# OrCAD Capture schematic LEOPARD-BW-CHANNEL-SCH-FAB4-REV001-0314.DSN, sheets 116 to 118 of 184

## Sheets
116 055_DDR4 DIMM CPU0 CHB-2: size A3; title: DDR4 DIMM CPU0 CHB-2
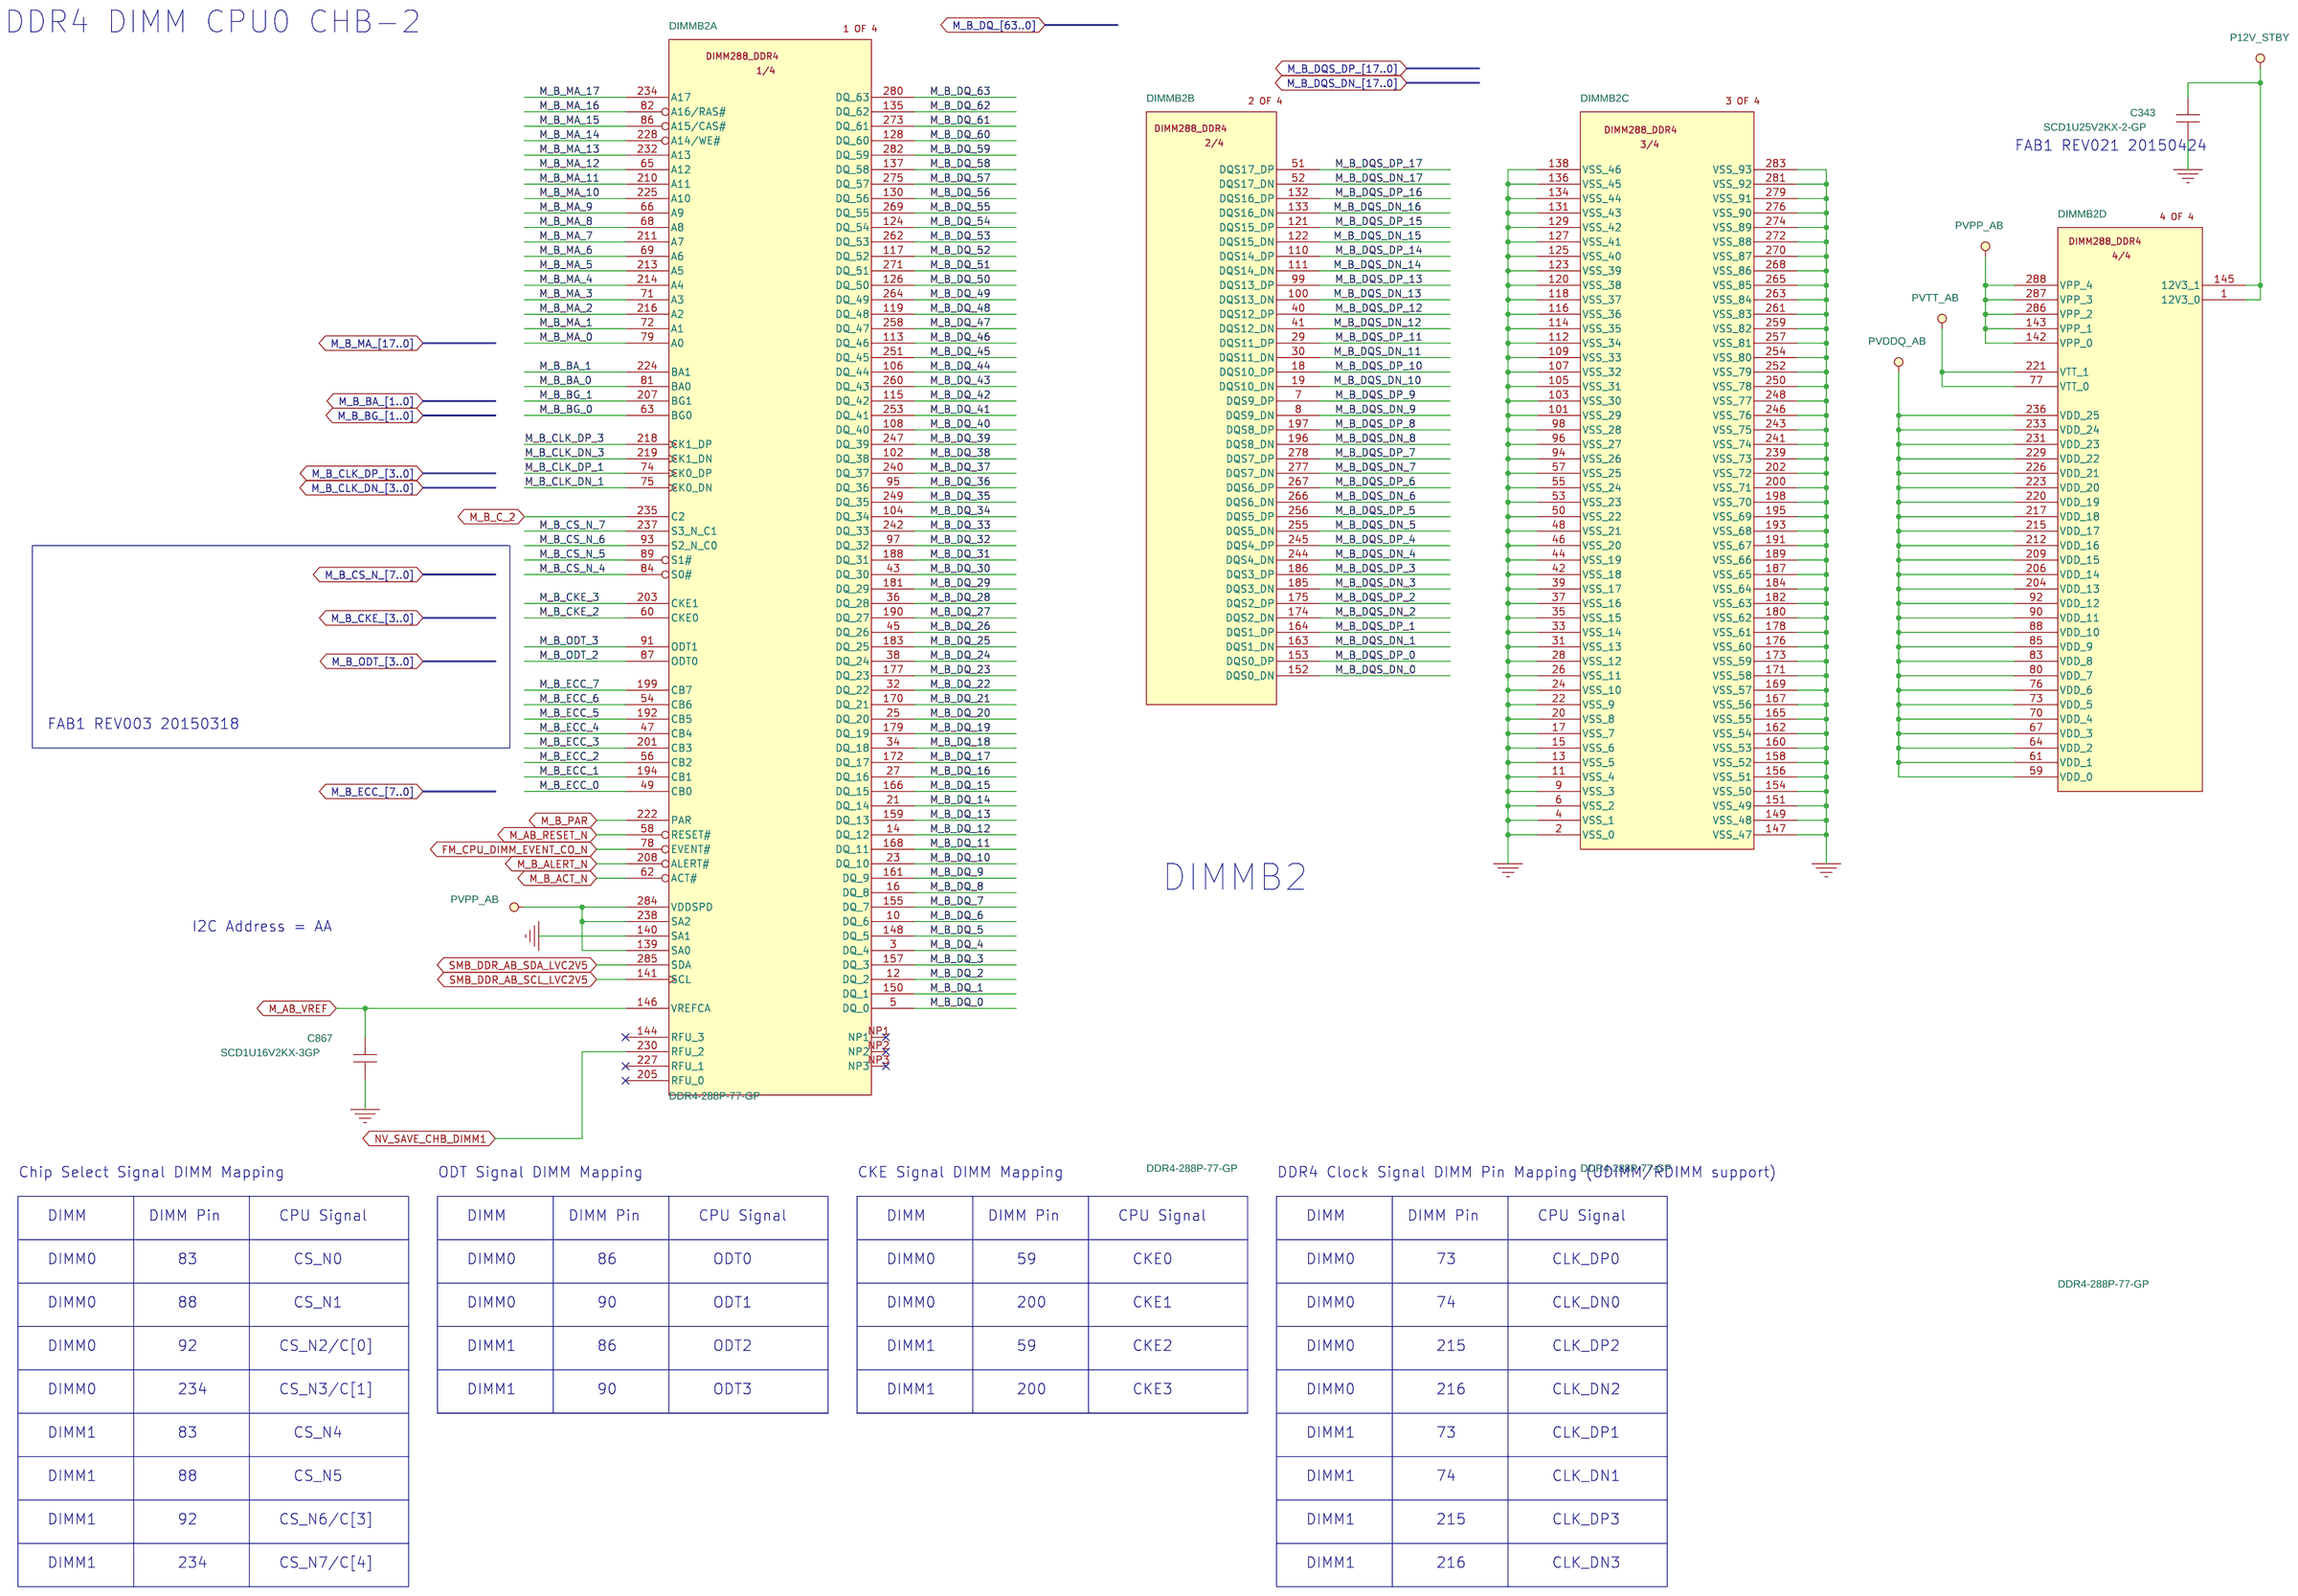
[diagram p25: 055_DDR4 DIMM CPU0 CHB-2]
117 054_DDR4 DIMM CPU0 CHB-1: size A3; title: DDR4 DIMM CPU0 CHB-1
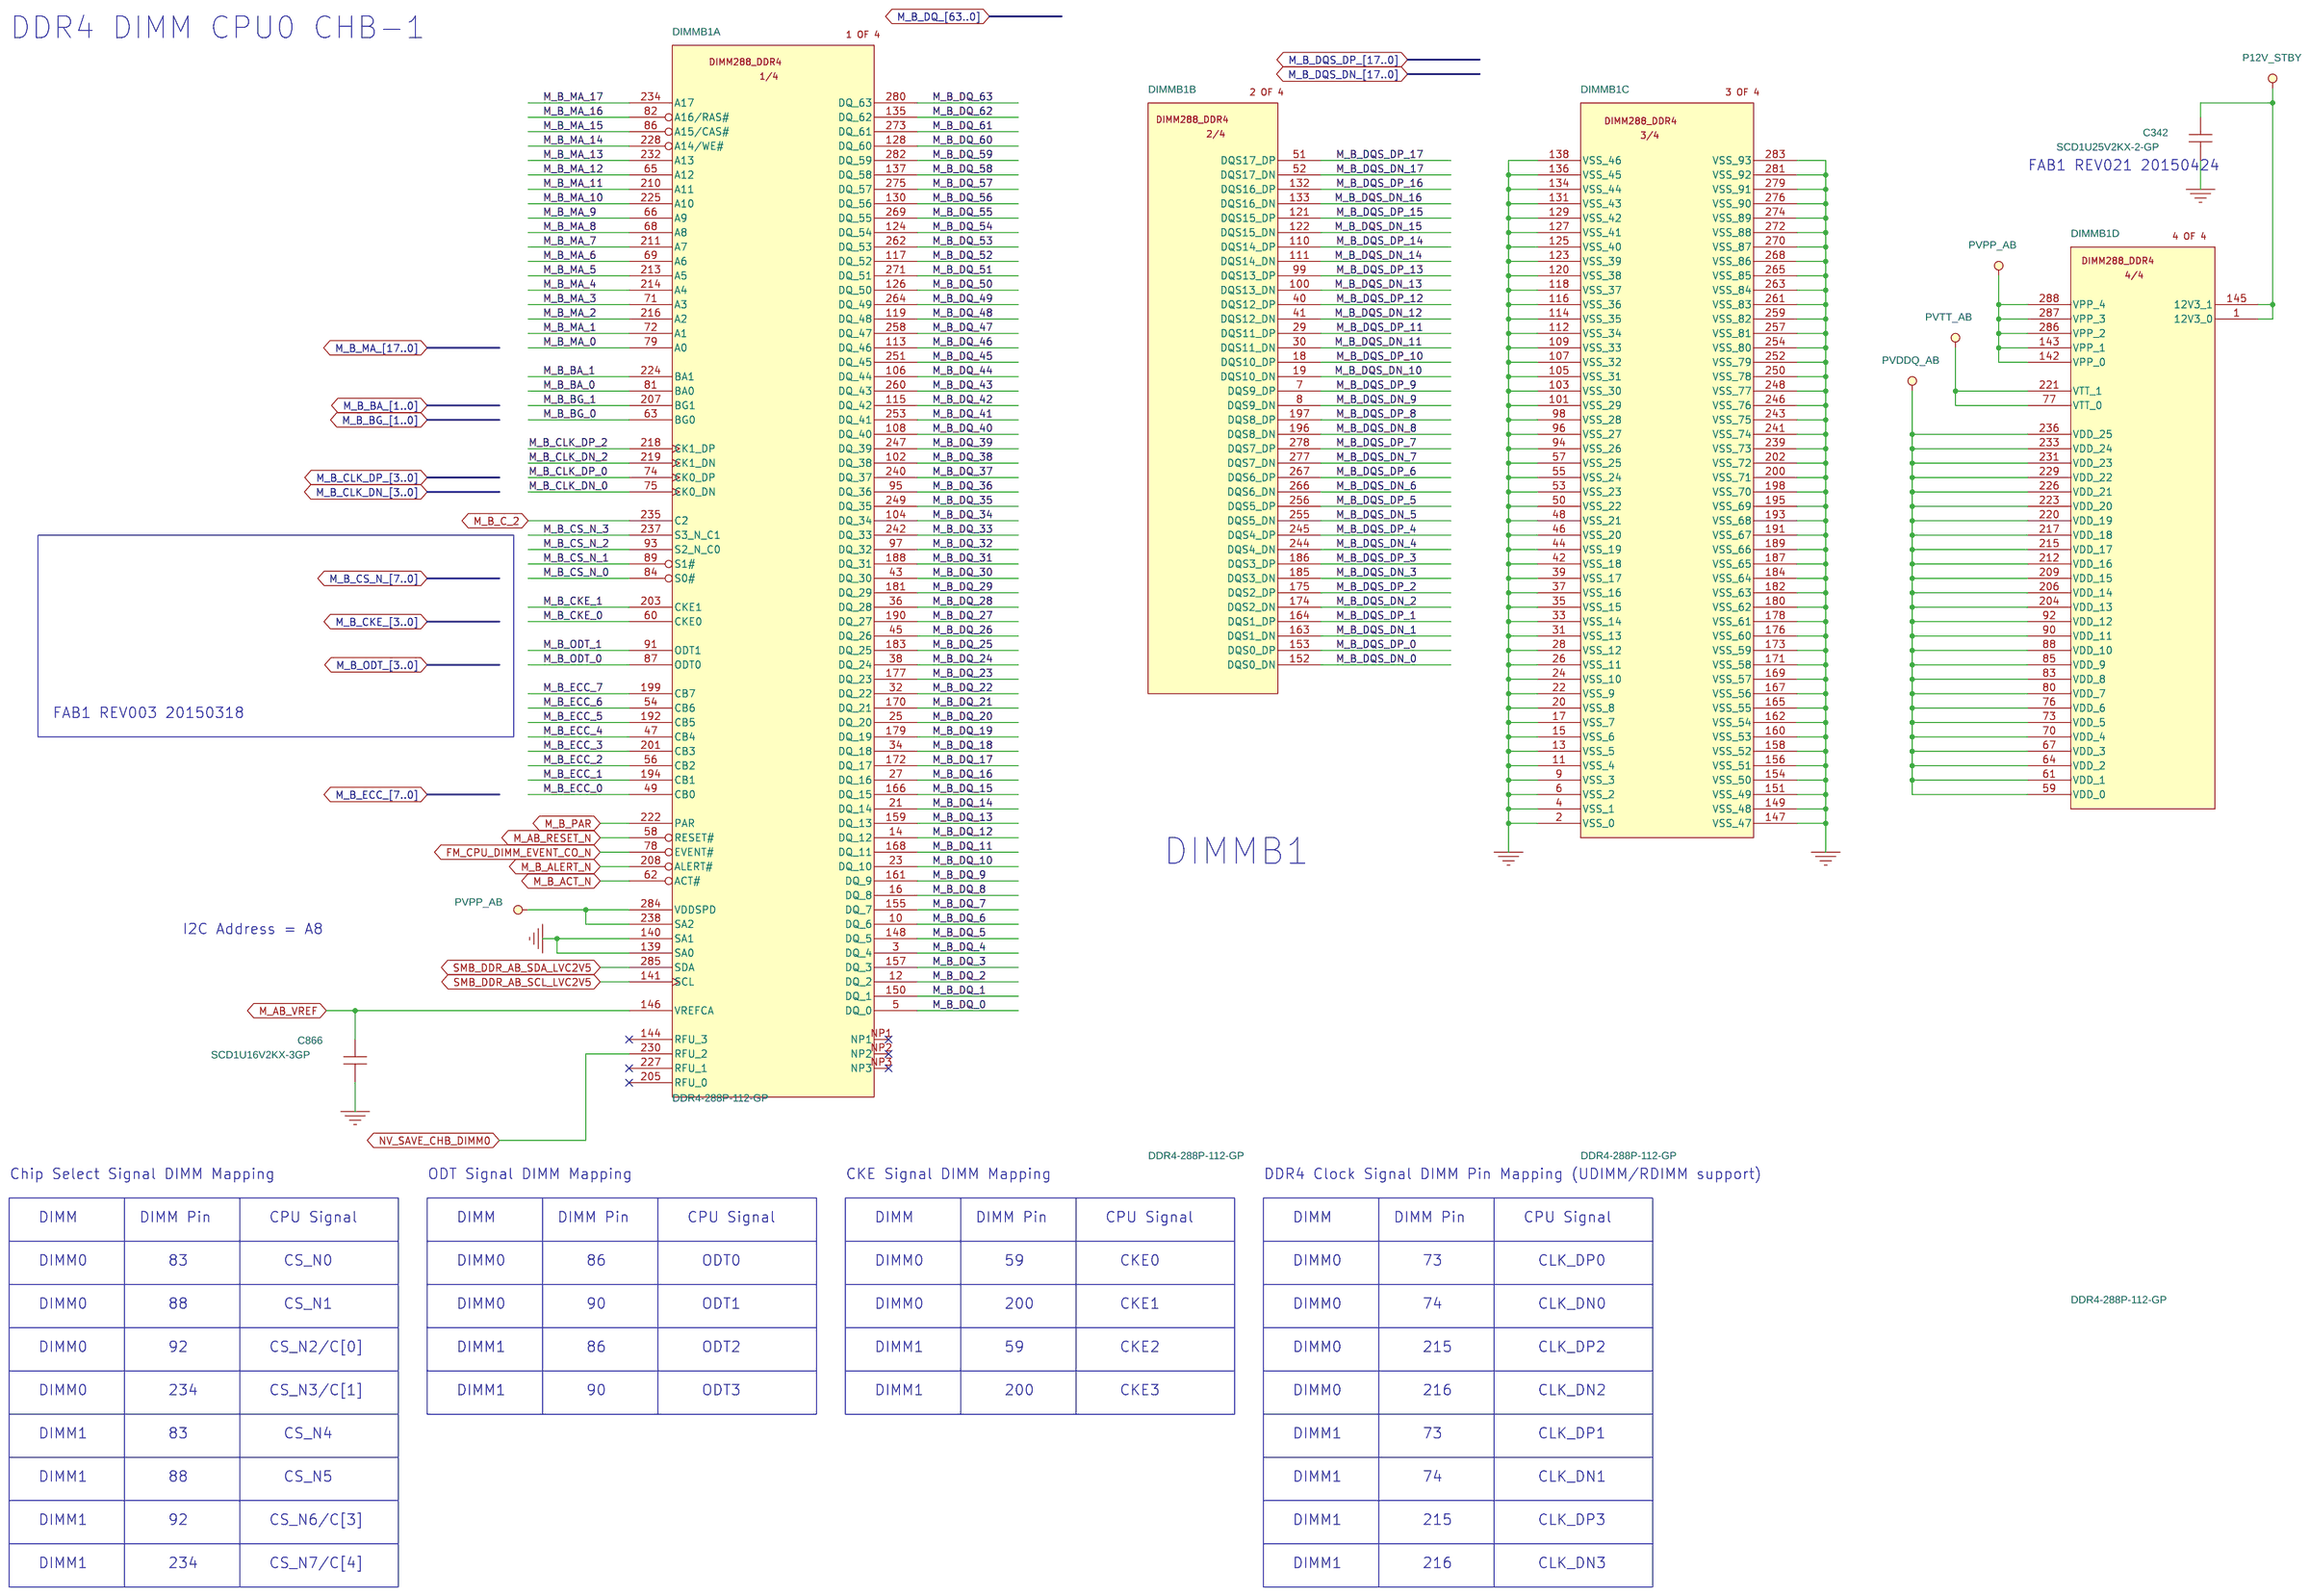
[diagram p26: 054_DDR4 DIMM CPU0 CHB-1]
118 053_DDR4 DIMM CPU0 CHA-2: size A3; title: DDR4 DIMM CPU0 CHA-2
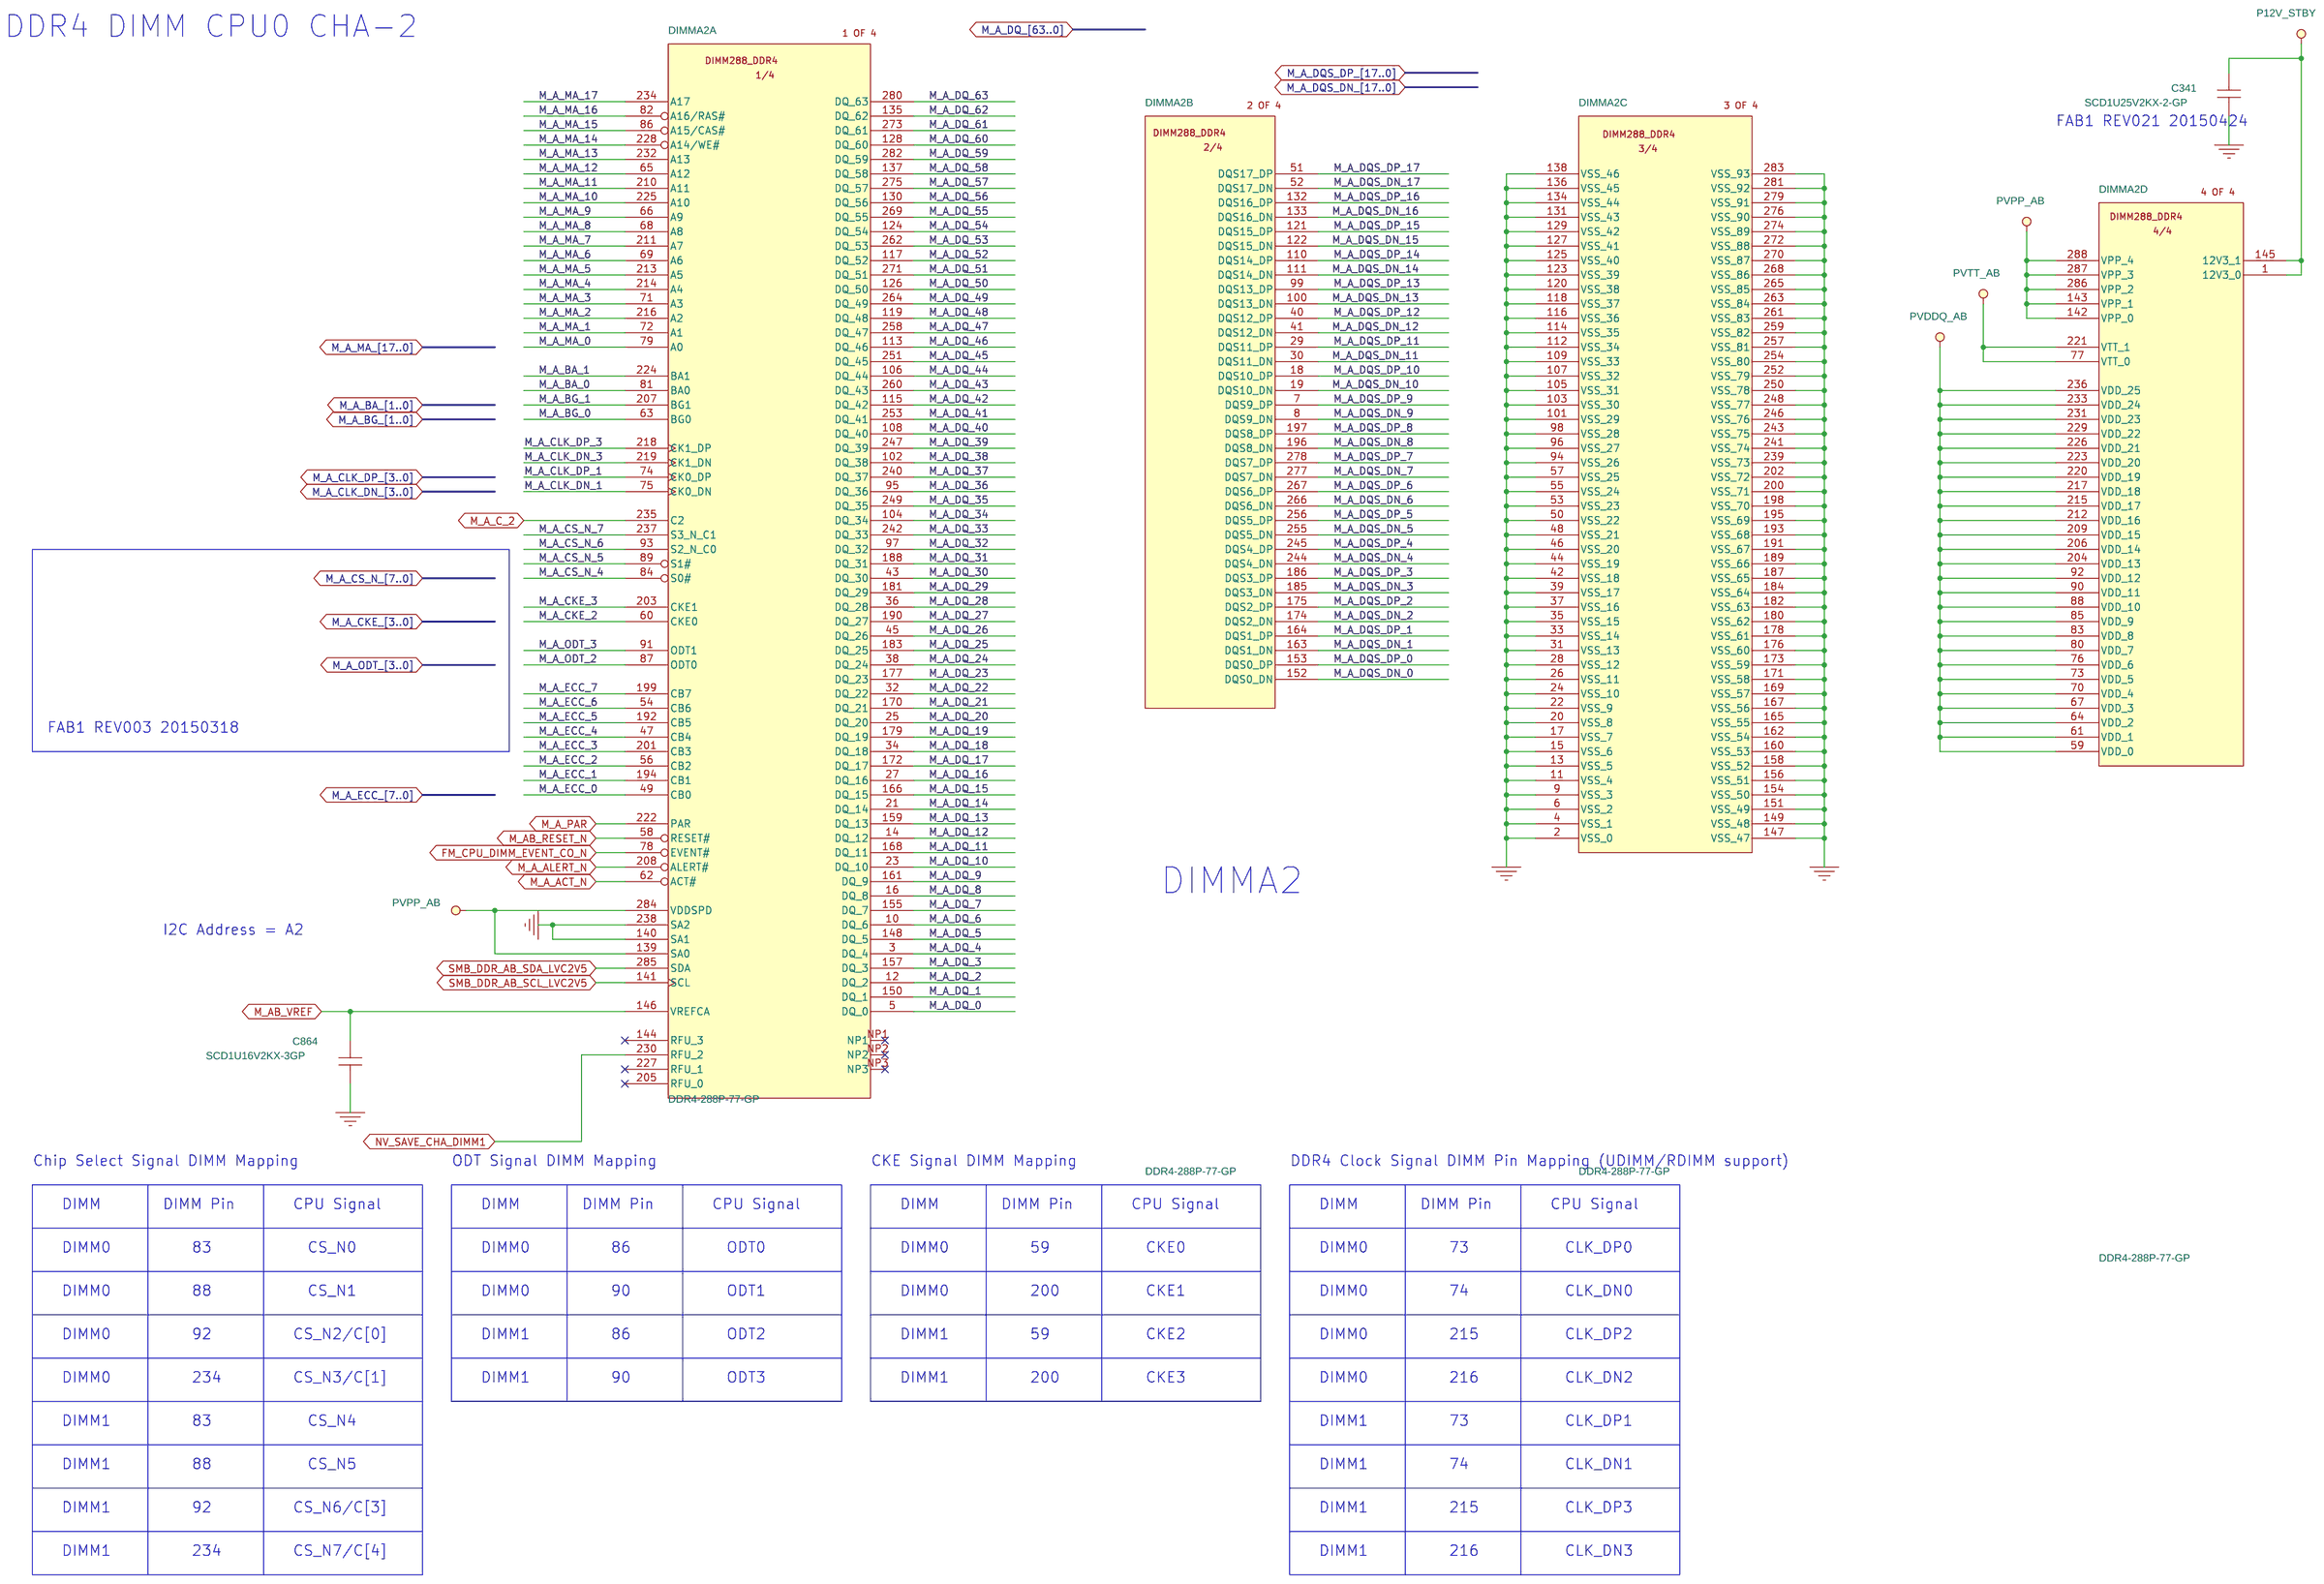
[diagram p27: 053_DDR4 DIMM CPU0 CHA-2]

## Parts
sheet 053_DDR4 DIMM CPU0 CHA-2
C341  SCD1U25V2KX-2-GP  [C402H22]
C864  SCD1U16V2KX-3GP  [C402H22]
DIMMA2  DDR4-288P-77-GP  [10124632-0001113LF]  (sections A,B,C,D)
sheet 054_DDR4 DIMM CPU0 CHB-1
C342  SCD1U25V2KX-2-GP  [C402H22]
C866  SCD1U16V2KX-3GP  [C402H22]
DIMMB1  DDR4-288P-112-GP  [10124632-0001113LF]  (sections A,B,C,D)
sheet 055_DDR4 DIMM CPU0 CHB-2
C343  SCD1U25V2KX-2-GP  [C402H22]
C867  SCD1U16V2KX-3GP  [C402H22]
DIMMB2  DDR4-288P-77-GP  [10124632-0001113LF]  (sections A,B,C,D)

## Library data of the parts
C341-C343 = SCD1U25V2KX-2-GP: CHIP CAP C 0.1U 25V K0402 X7R; GREENDFACTOR: R2_SA;HF_SA;G_SA;; Part Number: 78.10422.2FL; Part Type: SMD-BCG4; SPEC: http://wpqssvr.wistron.com.tw:7001/wpqs/servlet/COM.qpart.Attachment?PartNumber=78.10422.2FL
C864 C866 C867 = SCD1U16V2KX-3GP: CHIP CAP C 0.1U 16V K0402 X7R; CATEGORIES: CAP_1.xV; GREENDFACTOR: R2_SA;HF_SA;G_SA;; MAIN_SOURCE: M; Part Number: 78.10421.2FL; Part Type: SMD-BCG; SPEC: http://wpqssvr.wistron.com.tw:7001/wpqs/servlet/COM.qpart.Attachment?PartNumber=78.10421.2FL
DIMMA2 DIMMB2 = DDR4-288P-77-GP: SKT DIMM DDR4 288P 10124632-0001001LF; GREENDFACTOR: R2_SA;; POP?: 022.10010.0B11; Part Number: 22.10244.1A1; Part Type: SOCKET-G1; SPEC: http://wpqssvr.wistron.com.tw:7001/wpqs/servlet/COM.qpart.Attachment?PartNumber=22.10244.1A1
DIMMB1 = DDR4-288P-112-GP: SKT DIMM DDR4 288P 10124632-0003001LF; GREENDFACTOR: R2_C;; POP?: 022.10010.0E11; Part Number: 022.10010.0B91; Part Type: SOCKET-G2; SPEC: http://wpqssvr.wistron.com.tw:7001/wpqs/servlet/COM.qpart.Attachment?PartNumber=022.10010.0B91

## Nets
GND: C341.2 C342.2 C343.2 C864.2 C866.2 C867.2 DIMMA2.2(VSS_0) DIMMA2.4(VSS_1) DIMMA2.6(VSS_2) DIMMA2.9(VSS_3) DIMMA2.11(VSS_4) DIMMA2.13(VSS_5) DIMMA2.15(VSS_6) DIMMA2.17(VSS_7) DIMMA2.20(VSS_8) DIMMA2.22(VSS_9) DIMMA2.24(VSS_10) DIMMA2.26(VSS_11) DIMMA2.28(VSS_12) DIMMA2.31(VSS_13) DIMMA2.33(VSS_14) DIMMA2.35(VSS_15) DIMMA2.37(VSS_16) DIMMA2.39(VSS_17) DIMMA2.42(VSS_18) DIMMA2.44(VSS_19) DIMMA2.46(VSS_20) DIMMA2.48(VSS_21) DIMMA2.50(VSS_22) DIMMA2.53(VSS_23) DIMMA2.55(VSS_24) DIMMA2.57(VSS_25) DIMMA2.94(VSS_26) DIMMA2.96(VSS_27) DIMMA2.98(VSS_28) DIMMA2.101(VSS_29) DIMMA2.103(VSS_30) DIMMA2.105(VSS_31) DIMMA2.107(VSS_32) DIMMA2.109(VSS_33) DIMMA2.112(VSS_34) DIMMA2.114(VSS_35) DIMMA2.116(VSS_36) DIMMA2.118(VSS_37) DIMMA2.120(VSS_38) DIMMA2.123(VSS_39) DIMMA2.125(VSS_40) DIMMA2.127(VSS_41) DIMMA2.129(VSS_42) DIMMA2.131(VSS_43) DIMMA2.134(VSS_44) DIMMA2.136(VSS_45) DIMMA2.138(VSS_46) DIMMA2.140(SA1) DIMMA2.147(VSS_47) DIMMA2.149(VSS_48) DIMMA2.151(VSS_49) DIMMA2.154(VSS_50) DIMMA2.156(VSS_51) DIMMA2.158(VSS_52) DIMMA2.160(VSS_53) DIMMA2.162(VSS_54) DIMMA2.165(VSS_55) DIMMA2.167(VSS_56) DIMMA2.169(VSS_57) DIMMA2.171(VSS_58) DIMMA2.173(VSS_59) DIMMA2.176(VSS_60) DIMMA2.178(VSS_61) DIMMA2.180(VSS_62) DIMMA2.182(VSS_63) DIMMA2.184(VSS_64) DIMMA2.187(VSS_65) DIMMA2.189(VSS_66) DIMMA2.191(VSS_67) DIMMA2.193(VSS_68) DIMMA2.195(VSS_69) DIMMA2.198(VSS_70) DIMMA2.200(VSS_71) DIMMA2.202(VSS_72) DIMMA2.238(SA2) DIMMA2.239(VSS_73) DIMMA2.241(VSS_74) DIMMA2.243(VSS_75) DIMMA2.246(VSS_76) DIMMA2.248(VSS_77) DIMMA2.250(VSS_78) DIMMA2.252(VSS_79) DIMMA2.254(VSS_80) DIMMA2.257(VSS_81) DIMMA2.259(VSS_82) DIMMA2.261(VSS_83) DIMMA2.263(VSS_84) DIMMA2.265(VSS_85) DIMMA2.268(VSS_86) DIMMA2.270(VSS_87) DIMMA2.272(VSS_88) DIMMA2.274(VSS_89) DIMMA2.276(VSS_90) DIMMA2.279(VSS_91) DIMMA2.281(VSS_92) DIMMA2.283(VSS_93) DIMMB1.2(VSS_0) DIMMB1.4(VSS_1) DIMMB1.6(VSS_2) DIMMB1.9(VSS_3) DIMMB1.11(VSS_4) DIMMB1.13(VSS_5) DIMMB1.15(VSS_6) DIMMB1.17(VSS_7) DIMMB1.20(VSS_8) DIMMB1.22(VSS_9) DIMMB1.24(VSS_10) DIMMB1.26(VSS_11) DIMMB1.28(VSS_12) DIMMB1.31(VSS_13) DIMMB1.33(VSS_14) DIMMB1.35(VSS_15) DIMMB1.37(VSS_16) DIMMB1.39(VSS_17) DIMMB1.42(VSS_18) DIMMB1.44(VSS_19) DIMMB1.46(VSS_20) DIMMB1.48(VSS_21) DIMMB1.50(VSS_22) DIMMB1.53(VSS_23) DIMMB1.55(VSS_24) DIMMB1.57(VSS_25) DIMMB1.94(VSS_26) DIMMB1.96(VSS_27) DIMMB1.98(VSS_28) DIMMB1.101(VSS_29) DIMMB1.103(VSS_30) DIMMB1.105(VSS_31) DIMMB1.107(VSS_32) DIMMB1.109(VSS_33) DIMMB1.112(VSS_34) DIMMB1.114(VSS_35) DIMMB1.116(VSS_36) DIMMB1.118(VSS_37) DIMMB1.120(VSS_38) DIMMB1.123(VSS_39) DIMMB1.125(VSS_40) DIMMB1.127(VSS_41) DIMMB1.129(VSS_42) DIMMB1.131(VSS_43) DIMMB1.134(VSS_44) DIMMB1.136(VSS_45) DIMMB1.138(VSS_46) DIMMB1.139(SA0) DIMMB1.140(SA1) DIMMB1.147(VSS_47) DIMMB1.149(VSS_48) DIMMB1.151(VSS_49) DIMMB1.154(VSS_50) DIMMB1.156(VSS_51) DIMMB1.158(VSS_52) DIMMB1.160(VSS_53) DIMMB1.162(VSS_54) DIMMB1.165(VSS_55) DIMMB1.167(VSS_56) DIMMB1.169(VSS_57) DIMMB1.171(VSS_58) DIMMB1.173(VSS_59) DIMMB1.176(VSS_60) DIMMB1.178(VSS_61) DIMMB1.180(VSS_62) DIMMB1.182(VSS_63) DIMMB1.184(VSS_64) DIMMB1.187(VSS_65) DIMMB1.189(VSS_66) DIMMB1.191(VSS_67) DIMMB1.193(VSS_68) DIMMB1.195(VSS_69) DIMMB1.198(VSS_70) DIMMB1.200(VSS_71) DIMMB1.202(VSS_72) DIMMB1.239(VSS_73) DIMMB1.241(VSS_74) DIMMB1.243(VSS_75) DIMMB1.246(VSS_76) DIMMB1.248(VSS_77) DIMMB1.250(VSS_78) DIMMB1.252(VSS_79) DIMMB1.254(VSS_80) DIMMB1.257(VSS_81) DIMMB1.259(VSS_82) DIMMB1.261(VSS_83) DIMMB1.263(VSS_84) DIMMB1.265(VSS_85) DIMMB1.268(VSS_86) DIMMB1.270(VSS_87) DIMMB1.272(VSS_88) DIMMB1.274(VSS_89) DIMMB1.276(VSS_90) DIMMB1.279(VSS_91) DIMMB1.281(VSS_92) DIMMB1.283(VSS_93) DIMMB2.2(VSS_0) DIMMB2.4(VSS_1) DIMMB2.6(VSS_2) DIMMB2.9(VSS_3) DIMMB2.11(VSS_4) DIMMB2.13(VSS_5) DIMMB2.15(VSS_6) DIMMB2.17(VSS_7) DIMMB2.20(VSS_8) DIMMB2.22(VSS_9) DIMMB2.24(VSS_10) DIMMB2.26(VSS_11) DIMMB2.28(VSS_12) DIMMB2.31(VSS_13) DIMMB2.33(VSS_14) DIMMB2.35(VSS_15) DIMMB2.37(VSS_16) DIMMB2.39(VSS_17) DIMMB2.42(VSS_18) DIMMB2.44(VSS_19) DIMMB2.46(VSS_20) DIMMB2.48(VSS_21) DIMMB2.50(VSS_22) DIMMB2.53(VSS_23) DIMMB2.55(VSS_24) DIMMB2.57(VSS_25) DIMMB2.94(VSS_26) DIMMB2.96(VSS_27) DIMMB2.98(VSS_28) DIMMB2.101(VSS_29) DIMMB2.103(VSS_30) DIMMB2.105(VSS_31) DIMMB2.107(VSS_32) DIMMB2.109(VSS_33) DIMMB2.112(VSS_34) DIMMB2.114(VSS_35) DIMMB2.116(VSS_36) DIMMB2.118(VSS_37) DIMMB2.120(VSS_38) DIMMB2.123(VSS_39) DIMMB2.125(VSS_40) DIMMB2.127(VSS_41) DIMMB2.129(VSS_42) DIMMB2.131(VSS_43) DIMMB2.134(VSS_44) DIMMB2.136(VSS_45) DIMMB2.138(VSS_46) DIMMB2.140(SA1) DIMMB2.147(VSS_47) DIMMB2.149(VSS_48) DIMMB2.151(VSS_49) DIMMB2.154(VSS_50) DIMMB2.156(VSS_51) DIMMB2.158(VSS_52) DIMMB2.160(VSS_53) DIMMB2.162(VSS_54) DIMMB2.165(VSS_55) DIMMB2.167(VSS_56) DIMMB2.169(VSS_57) DIMMB2.171(VSS_58) DIMMB2.173(VSS_59) DIMMB2.176(VSS_60) DIMMB2.178(VSS_61) DIMMB2.180(VSS_62) DIMMB2.182(VSS_63) DIMMB2.184(VSS_64) DIMMB2.187(VSS_65) DIMMB2.189(VSS_66) DIMMB2.191(VSS_67) DIMMB2.193(VSS_68) DIMMB2.195(VSS_69) DIMMB2.198(VSS_70) DIMMB2.200(VSS_71) DIMMB2.202(VSS_72) DIMMB2.239(VSS_73) DIMMB2.241(VSS_74) DIMMB2.243(VSS_75) DIMMB2.246(VSS_76) DIMMB2.248(VSS_77) DIMMB2.250(VSS_78) DIMMB2.252(VSS_79) DIMMB2.254(VSS_80) DIMMB2.257(VSS_81) DIMMB2.259(VSS_82) DIMMB2.261(VSS_83) DIMMB2.263(VSS_84) DIMMB2.265(VSS_85) DIMMB2.268(VSS_86) DIMMB2.270(VSS_87) DIMMB2.272(VSS_88) DIMMB2.274(VSS_89) DIMMB2.276(VSS_90) DIMMB2.279(VSS_91) DIMMB2.281(VSS_92) DIMMB2.283(VSS_93) ; also on sheet 1 2 3 4 5 6 7 8 9 10 11 12 13 14 15 16 17 18 19 20 21 22 23 24 25 26 27 28 29 30 31 32 33 34 35 36 37 38 39 44 46 47 49 50 51 52 53 54 55 56 57 58 59 60 61 62 63 64 65 66 69 70 71 73 74 75 76 78 79 80 81 82 83 84 86 87 88 89 90 91 92 93 94 95 96 97 98 99 100 101 102 103 104 105 106 107 108 109 110 111 112 113 114 115 119 128 129 138 139 159 160 161 166 168 169 170 171 172 173 174 175 176 177 180 181 182 183 184
P12V_STBY: C341.1 C342.1 C343.1 DIMMA2.1(12V3_0) DIMMA2.145(12V3_1) DIMMB1.1(12V3_0) DIMMB1.145(12V3_1) DIMMB2.1(12V3_0) DIMMB2.145(12V3_1) ; also on sheet 2 3 4 7 9 10 11 12 13 17 18 22 23 27 28 32 36 59 60 75 95 104 105 106 107 108 109 110 111 112 113 114 115 119
PVDDQ_AB: DIMMA2.59(VDD_0) DIMMA2.61(VDD_1) DIMMA2.64(VDD_2) DIMMA2.67(VDD_3) DIMMA2.70(VDD_4) DIMMA2.73(VDD_5) DIMMA2.76(VDD_6) DIMMA2.80(VDD_7) DIMMA2.83(VDD_8) DIMMA2.85(VDD_9) DIMMA2.88(VDD_10) DIMMA2.90(VDD_11) DIMMA2.92(VDD_12) DIMMA2.204(VDD_13) DIMMA2.206(VDD_14) DIMMA2.209(VDD_15) DIMMA2.212(VDD_16) DIMMA2.215(VDD_17) DIMMA2.217(VDD_18) DIMMA2.220(VDD_19) DIMMA2.223(VDD_20) DIMMA2.226(VDD_21) DIMMA2.229(VDD_22) DIMMA2.231(VDD_23) DIMMA2.233(VDD_24) DIMMA2.236(VDD_25) DIMMB1.59(VDD_0) DIMMB1.61(VDD_1) DIMMB1.64(VDD_2) DIMMB1.67(VDD_3) DIMMB1.70(VDD_4) DIMMB1.73(VDD_5) DIMMB1.76(VDD_6) DIMMB1.80(VDD_7) DIMMB1.83(VDD_8) DIMMB1.85(VDD_9) DIMMB1.88(VDD_10) DIMMB1.90(VDD_11) DIMMB1.92(VDD_12) DIMMB1.204(VDD_13) DIMMB1.206(VDD_14) DIMMB1.209(VDD_15) DIMMB1.212(VDD_16) DIMMB1.215(VDD_17) DIMMB1.217(VDD_18) DIMMB1.220(VDD_19) DIMMB1.223(VDD_20) DIMMB1.226(VDD_21) DIMMB1.229(VDD_22) DIMMB1.231(VDD_23) DIMMB1.233(VDD_24) DIMMB1.236(VDD_25) DIMMB2.59(VDD_0) DIMMB2.61(VDD_1) DIMMB2.64(VDD_2) DIMMB2.67(VDD_3) DIMMB2.70(VDD_4) DIMMB2.73(VDD_5) DIMMB2.76(VDD_6) DIMMB2.80(VDD_7) DIMMB2.83(VDD_8) DIMMB2.85(VDD_9) DIMMB2.88(VDD_10) DIMMB2.90(VDD_11) DIMMB2.92(VDD_12) DIMMB2.204(VDD_13) DIMMB2.206(VDD_14) DIMMB2.209(VDD_15) DIMMB2.212(VDD_16) DIMMB2.215(VDD_17) DIMMB2.217(VDD_18) DIMMB2.220(VDD_19) DIMMB2.223(VDD_20) DIMMB2.226(VDD_21) DIMMB2.229(VDD_22) DIMMB2.231(VDD_23) DIMMB2.233(VDD_24) DIMMB2.236(VDD_25) ; also on sheet 28 30 45 52 97 119 130 139
FM_CPU_DIMM_EVENT_CO_N: DIMMA2.78(EVENT#) DIMMB1.78(EVENT#) DIMMB2.78(EVENT#) ; also on sheet 98 104 105 106 107 108 109 110 111 112 113 114 115 119
M_A_ACT_N: DIMMA2.62(ACT#) ; also on sheet 119 137
M_A_ALERT_N: DIMMA2.208(ALERT#) ; also on sheet 119 137
M_A_BA_0: DIMMA2.81(BA0) ; also on sheet 119 137
M_A_BA_1: DIMMA2.224(BA1) ; also on sheet 119 137
M_A_BG_0: DIMMA2.63(BG0) ; also on sheet 119 137
M_A_BG_1: DIMMA2.207(BG1) ; also on sheet 119 137
M_A_C_2: DIMMA2.235(C2) ; also on sheet 119 137
M_A_CKE_2: DIMMA2.60(CKE0) ; also on sheet 137
M_A_CKE_3: DIMMA2.203(CKE1) ; also on sheet 137
M_A_CLK_DN_1: DIMMA2.75(CK0_DN) ; also on sheet 137
M_A_CLK_DN_3: DIMMA2.219(CK1_DN) ; also on sheet 137
M_A_CLK_DP_1: DIMMA2.74(CK0_DP) ; also on sheet 137
M_A_CLK_DP_3: DIMMA2.218(CK1_DP) ; also on sheet 137
M_A_CS_N_4: DIMMA2.84(S0#) ; also on sheet 137
M_A_CS_N_5: DIMMA2.89(S1#) ; also on sheet 137
M_A_CS_N_6: DIMMA2.93(S2_N_C0) ; also on sheet 137
M_A_CS_N_7: DIMMA2.237(S3_N_C1) ; also on sheet 137
M_A_DQ_0: DIMMA2.5(DQ_0) ; also on sheet 119 137
M_A_DQ_1: DIMMA2.150(DQ_1) ; also on sheet 119 137
M_A_DQ_2: DIMMA2.12(DQ_2) ; also on sheet 119 137
M_A_DQ_3: DIMMA2.157(DQ_3) ; also on sheet 119 137
M_A_DQ_4: DIMMA2.3(DQ_4) ; also on sheet 119 137
M_A_DQ_5: DIMMA2.148(DQ_5) ; also on sheet 119 137
M_A_DQ_6: DIMMA2.10(DQ_6) ; also on sheet 119 137
M_A_DQ_7: DIMMA2.155(DQ_7) ; also on sheet 119 137
M_A_DQ_8: DIMMA2.16(DQ_8) ; also on sheet 119 137
M_A_DQ_9: DIMMA2.161(DQ_9) ; also on sheet 119 137
M_A_DQ_10: DIMMA2.23(DQ_10) ; also on sheet 119 137
M_A_DQ_11: DIMMA2.168(DQ_11) ; also on sheet 119 137
M_A_DQ_12: DIMMA2.14(DQ_12) ; also on sheet 119 137
M_A_DQ_13: DIMMA2.159(DQ_13) ; also on sheet 119 137
M_A_DQ_14: DIMMA2.21(DQ_14) ; also on sheet 119 137
M_A_DQ_15: DIMMA2.166(DQ_15) ; also on sheet 119 137
M_A_DQ_16: DIMMA2.27(DQ_16) ; also on sheet 119 137
M_A_DQ_17: DIMMA2.172(DQ_17) ; also on sheet 119 137
M_A_DQ_18: DIMMA2.34(DQ_18) ; also on sheet 119 137
M_A_DQ_19: DIMMA2.179(DQ_19) ; also on sheet 119 137
M_A_DQ_20: DIMMA2.25(DQ_20) ; also on sheet 119 137
M_A_DQ_21: DIMMA2.170(DQ_21) ; also on sheet 119 137
M_A_DQ_22: DIMMA2.32(DQ_22) ; also on sheet 119 137
M_A_DQ_23: DIMMA2.177(DQ_23) ; also on sheet 119 137
M_A_DQ_24: DIMMA2.38(DQ_24) ; also on sheet 119 137
M_A_DQ_25: DIMMA2.183(DQ_25) ; also on sheet 119 137
M_A_DQ_26: DIMMA2.45(DQ_26) ; also on sheet 119 137
M_A_DQ_27: DIMMA2.190(DQ_27) ; also on sheet 119 137
M_A_DQ_28: DIMMA2.36(DQ_28) ; also on sheet 119 137
M_A_DQ_29: DIMMA2.181(DQ_29) ; also on sheet 119 137
M_A_DQ_30: DIMMA2.43(DQ_30) ; also on sheet 119 137
M_A_DQ_31: DIMMA2.188(DQ_31) ; also on sheet 119 137
M_A_DQ_32: DIMMA2.97(DQ_32) ; also on sheet 119 137
M_A_DQ_33: DIMMA2.242(DQ_33) ; also on sheet 119 137
M_A_DQ_34: DIMMA2.104(DQ_34) ; also on sheet 119 137
M_A_DQ_35: DIMMA2.249(DQ_35) ; also on sheet 119 137
M_A_DQ_36: DIMMA2.95(DQ_36) ; also on sheet 119 137
M_A_DQ_37: DIMMA2.240(DQ_37) ; also on sheet 119 137
M_A_DQ_38: DIMMA2.102(DQ_38) ; also on sheet 119 137
M_A_DQ_39: DIMMA2.247(DQ_39) ; also on sheet 119 137
M_A_DQ_40: DIMMA2.108(DQ_40) ; also on sheet 119 137
M_A_DQ_41: DIMMA2.253(DQ_41) ; also on sheet 119 137
M_A_DQ_42: DIMMA2.115(DQ_42) ; also on sheet 119 137
M_A_DQ_43: DIMMA2.260(DQ_43) ; also on sheet 119 137
M_A_DQ_44: DIMMA2.106(DQ_44) ; also on sheet 119 137
M_A_DQ_45: DIMMA2.251(DQ_45) ; also on sheet 119 137
M_A_DQ_46: DIMMA2.113(DQ_46) ; also on sheet 119 137
M_A_DQ_47: DIMMA2.258(DQ_47) ; also on sheet 119 137
M_A_DQ_48: DIMMA2.119(DQ_48) ; also on sheet 119 137
M_A_DQ_49: DIMMA2.264(DQ_49) ; also on sheet 119 137
M_A_DQ_50: DIMMA2.126(DQ_50) ; also on sheet 119 137
M_A_DQ_51: DIMMA2.271(DQ_51) ; also on sheet 119 137
M_A_DQ_52: DIMMA2.117(DQ_52) ; also on sheet 119 137
M_A_DQ_53: DIMMA2.262(DQ_53) ; also on sheet 119 137
M_A_DQ_54: DIMMA2.124(DQ_54) ; also on sheet 119 137
M_A_DQ_55: DIMMA2.269(DQ_55) ; also on sheet 119 137
M_A_DQ_56: DIMMA2.130(DQ_56) ; also on sheet 119 137
M_A_DQ_57: DIMMA2.275(DQ_57) ; also on sheet 119 137
M_A_DQ_58: DIMMA2.137(DQ_58) ; also on sheet 119 137
M_A_DQ_59: DIMMA2.282(DQ_59) ; also on sheet 119 137
M_A_DQ_60: DIMMA2.128(DQ_60) ; also on sheet 119 137
M_A_DQ_61: DIMMA2.273(DQ_61) ; also on sheet 119 137
M_A_DQ_62: DIMMA2.135(DQ_62) ; also on sheet 119 137
M_A_DQ_63: DIMMA2.280(DQ_63) ; also on sheet 119 137
M_A_DQS_DN_0: DIMMA2.152(DQS0_DN) ; also on sheet 119 137
M_A_DQS_DN_1: DIMMA2.163(DQS1_DN) ; also on sheet 119 137
M_A_DQS_DN_2: DIMMA2.174(DQS2_DN) ; also on sheet 119 137
M_A_DQS_DN_3: DIMMA2.185(DQS3_DN) ; also on sheet 119 137
M_A_DQS_DN_4: DIMMA2.244(DQS4_DN) ; also on sheet 119 137
M_A_DQS_DN_5: DIMMA2.255(DQS5_DN) ; also on sheet 119 137
M_A_DQS_DN_6: DIMMA2.266(DQS6_DN) ; also on sheet 119 137
M_A_DQS_DN_7: DIMMA2.277(DQS7_DN) ; also on sheet 119 137
M_A_DQS_DN_8: DIMMA2.196(DQS8_DN) ; also on sheet 119 137
M_A_DQS_DN_9: DIMMA2.8(DQS9_DN) ; also on sheet 119 137
M_A_DQS_DN_10: DIMMA2.19(DQS10_DN) ; also on sheet 119 137
M_A_DQS_DN_11: DIMMA2.30(DQS11_DN) ; also on sheet 119 137
M_A_DQS_DN_12: DIMMA2.41(DQS12_DN) ; also on sheet 119 137
M_A_DQS_DN_13: DIMMA2.100(DQS13_DN) ; also on sheet 119 137
M_A_DQS_DN_14: DIMMA2.111(DQS14_DN) ; also on sheet 119 137
M_A_DQS_DN_15: DIMMA2.122(DQS15_DN) ; also on sheet 119 137
M_A_DQS_DN_16: DIMMA2.133(DQS16_DN) ; also on sheet 119 137
M_A_DQS_DN_17: DIMMA2.52(DQS17_DN) ; also on sheet 119 137
M_A_DQS_DP_0: DIMMA2.153(DQS0_DP) ; also on sheet 119 137
M_A_DQS_DP_1: DIMMA2.164(DQS1_DP) ; also on sheet 119 137
M_A_DQS_DP_2: DIMMA2.175(DQS2_DP) ; also on sheet 119 137
M_A_DQS_DP_3: DIMMA2.186(DQS3_DP) ; also on sheet 119 137
M_A_DQS_DP_4: DIMMA2.245(DQS4_DP) ; also on sheet 119 137
M_A_DQS_DP_5: DIMMA2.256(DQS5_DP) ; also on sheet 119 137
M_A_DQS_DP_6: DIMMA2.267(DQS6_DP) ; also on sheet 119 137
M_A_DQS_DP_7: DIMMA2.278(DQS7_DP) ; also on sheet 119 137
M_A_DQS_DP_8: DIMMA2.197(DQS8_DP) ; also on sheet 119 137
M_A_DQS_DP_9: DIMMA2.7(DQS9_DP) ; also on sheet 119 137
M_A_DQS_DP_10: DIMMA2.18(DQS10_DP) ; also on sheet 119 137
M_A_DQS_DP_11: DIMMA2.29(DQS11_DP) ; also on sheet 119 137
M_A_DQS_DP_12: DIMMA2.40(DQS12_DP) ; also on sheet 119 137
M_A_DQS_DP_13: DIMMA2.99(DQS13_DP) ; also on sheet 119 137
M_A_DQS_DP_14: DIMMA2.110(DQS14_DP) ; also on sheet 119 137
M_A_DQS_DP_15: DIMMA2.121(DQS15_DP) ; also on sheet 119 137
M_A_DQS_DP_16: DIMMA2.132(DQS16_DP) ; also on sheet 119 137
M_A_DQS_DP_17: DIMMA2.51(DQS17_DP) ; also on sheet 119 137
M_A_ECC_0: DIMMA2.49(CB0) ; also on sheet 119 137
M_A_ECC_1: DIMMA2.194(CB1) ; also on sheet 119 137
M_A_ECC_2: DIMMA2.56(CB2) ; also on sheet 119 137
M_A_ECC_3: DIMMA2.201(CB3) ; also on sheet 119 137
M_A_ECC_4: DIMMA2.47(CB4) ; also on sheet 119 137
M_A_ECC_5: DIMMA2.192(CB5) ; also on sheet 119 137
M_A_ECC_6: DIMMA2.54(CB6) ; also on sheet 119 137
M_A_ECC_7: DIMMA2.199(CB7) ; also on sheet 119 137
M_A_MA_0: DIMMA2.79(A0) ; also on sheet 119 137
M_A_MA_1: DIMMA2.72(A1) ; also on sheet 119 137
M_A_MA_2: DIMMA2.216(A2) ; also on sheet 119 137
M_A_MA_3: DIMMA2.71(A3) ; also on sheet 119 137
M_A_MA_4: DIMMA2.214(A4) ; also on sheet 119 137
M_A_MA_5: DIMMA2.213(A5) ; also on sheet 119 137
M_A_MA_6: DIMMA2.69(A6) ; also on sheet 119 137
M_A_MA_7: DIMMA2.211(A7) ; also on sheet 119 137
M_A_MA_8: DIMMA2.68(A8) ; also on sheet 119 137
M_A_MA_9: DIMMA2.66(A9) ; also on sheet 119 137
M_A_MA_10: DIMMA2.225(A10) ; also on sheet 119 137
M_A_MA_11: DIMMA2.210(A11) ; also on sheet 119 137
M_A_MA_12: DIMMA2.65(A12) ; also on sheet 119 137
M_A_MA_13: DIMMA2.232(A13) ; also on sheet 119 137
M_A_MA_14: DIMMA2.228(A14/WE#) ; also on sheet 119 137
M_A_MA_15: DIMMA2.86(A15/CAS#) ; also on sheet 119 137
M_A_MA_16: DIMMA2.82(A16/RAS#) ; also on sheet 119 137
M_A_MA_17: DIMMA2.234(A17) ; also on sheet 119 137
M_A_ODT_2: DIMMA2.87(ODT0) ; also on sheet 137
M_A_ODT_3: DIMMA2.91(ODT1) ; also on sheet 137
M_A_PAR: DIMMA2.222(PAR) ; also on sheet 119 137
M_AB_RESET_N: DIMMA2.58(RESET#) DIMMB1.58(RESET#) DIMMB2.58(RESET#) ; also on sheet 119 139
M_AB_VREF: C864.1 C866.1 C867.1 DIMMA2.146(VREFCA) DIMMB1.146(VREFCA) DIMMB2.146(VREFCA) ; also on sheet 119 139
M_B_ACT_N: DIMMB1.62(ACT#) DIMMB2.62(ACT#) ; also on sheet 136
M_B_ALERT_N: DIMMB1.208(ALERT#) DIMMB2.208(ALERT#) ; also on sheet 136
M_B_BA_0: DIMMB1.81(BA0) DIMMB2.81(BA0) ; also on sheet 136
M_B_BA_1: DIMMB1.224(BA1) DIMMB2.224(BA1) ; also on sheet 136
M_B_BG_0: DIMMB1.63(BG0) DIMMB2.63(BG0) ; also on sheet 136
M_B_BG_1: DIMMB1.207(BG1) DIMMB2.207(BG1) ; also on sheet 136
M_B_C_2: DIMMB1.235(C2) DIMMB2.235(C2) ; also on sheet 136
M_B_CKE_0: DIMMB1.60(CKE0) ; also on sheet 136
M_B_CKE_1: DIMMB1.203(CKE1) ; also on sheet 136
M_B_CKE_2: DIMMB2.60(CKE0) ; also on sheet 136
M_B_CKE_3: DIMMB2.203(CKE1) ; also on sheet 136
M_B_CLK_DN_0: DIMMB1.75(CK0_DN) ; also on sheet 136
M_B_CLK_DN_1: DIMMB2.75(CK0_DN) ; also on sheet 136
M_B_CLK_DN_2: DIMMB1.219(CK1_DN) ; also on sheet 136
M_B_CLK_DN_3: DIMMB2.219(CK1_DN) ; also on sheet 136
M_B_CLK_DP_0: DIMMB1.74(CK0_DP) ; also on sheet 136
M_B_CLK_DP_1: DIMMB2.74(CK0_DP) ; also on sheet 136
M_B_CLK_DP_2: DIMMB1.218(CK1_DP) ; also on sheet 136
M_B_CLK_DP_3: DIMMB2.218(CK1_DP) ; also on sheet 136
M_B_CS_N_0: DIMMB1.84(S0#) ; also on sheet 136
M_B_CS_N_1: DIMMB1.89(S1#) ; also on sheet 136
M_B_CS_N_2: DIMMB1.93(S2_N_C0) ; also on sheet 136
M_B_CS_N_3: DIMMB1.237(S3_N_C1) ; also on sheet 136
M_B_CS_N_4: DIMMB2.84(S0#) ; also on sheet 136
M_B_CS_N_5: DIMMB2.89(S1#) ; also on sheet 136
M_B_CS_N_6: DIMMB2.93(S2_N_C0) ; also on sheet 136
M_B_CS_N_7: DIMMB2.237(S3_N_C1) ; also on sheet 136
M_B_DQ_0: DIMMB1.5(DQ_0) DIMMB2.5(DQ_0) ; also on sheet 136
M_B_DQ_1: DIMMB1.150(DQ_1) DIMMB2.150(DQ_1) ; also on sheet 136
M_B_DQ_2: DIMMB1.12(DQ_2) DIMMB2.12(DQ_2) ; also on sheet 136
M_B_DQ_3: DIMMB1.157(DQ_3) DIMMB2.157(DQ_3) ; also on sheet 136
M_B_DQ_4: DIMMB1.3(DQ_4) DIMMB2.3(DQ_4) ; also on sheet 136
M_B_DQ_5: DIMMB1.148(DQ_5) DIMMB2.148(DQ_5) ; also on sheet 136
M_B_DQ_6: DIMMB1.10(DQ_6) DIMMB2.10(DQ_6) ; also on sheet 136
M_B_DQ_7: DIMMB1.155(DQ_7) DIMMB2.155(DQ_7) ; also on sheet 136
M_B_DQ_8: DIMMB1.16(DQ_8) DIMMB2.16(DQ_8) ; also on sheet 136
M_B_DQ_9: DIMMB1.161(DQ_9) DIMMB2.161(DQ_9) ; also on sheet 136
M_B_DQ_10: DIMMB1.23(DQ_10) DIMMB2.23(DQ_10) ; also on sheet 136
M_B_DQ_11: DIMMB1.168(DQ_11) DIMMB2.168(DQ_11) ; also on sheet 136
M_B_DQ_12: DIMMB1.14(DQ_12) DIMMB2.14(DQ_12) ; also on sheet 136
M_B_DQ_13: DIMMB1.159(DQ_13) DIMMB2.159(DQ_13) ; also on sheet 136
M_B_DQ_14: DIMMB1.21(DQ_14) DIMMB2.21(DQ_14) ; also on sheet 136
M_B_DQ_15: DIMMB1.166(DQ_15) DIMMB2.166(DQ_15) ; also on sheet 136
M_B_DQ_16: DIMMB1.27(DQ_16) DIMMB2.27(DQ_16) ; also on sheet 136
M_B_DQ_17: DIMMB1.172(DQ_17) DIMMB2.172(DQ_17) ; also on sheet 136
M_B_DQ_18: DIMMB1.34(DQ_18) DIMMB2.34(DQ_18) ; also on sheet 136
M_B_DQ_19: DIMMB1.179(DQ_19) DIMMB2.179(DQ_19) ; also on sheet 136
M_B_DQ_20: DIMMB1.25(DQ_20) DIMMB2.25(DQ_20) ; also on sheet 136
M_B_DQ_21: DIMMB1.170(DQ_21) DIMMB2.170(DQ_21) ; also on sheet 136
M_B_DQ_22: DIMMB1.32(DQ_22) DIMMB2.32(DQ_22) ; also on sheet 136
M_B_DQ_23: DIMMB1.177(DQ_23) DIMMB2.177(DQ_23) ; also on sheet 136
M_B_DQ_24: DIMMB1.38(DQ_24) DIMMB2.38(DQ_24) ; also on sheet 136
M_B_DQ_25: DIMMB1.183(DQ_25) DIMMB2.183(DQ_25) ; also on sheet 136
M_B_DQ_26: DIMMB1.45(DQ_26) DIMMB2.45(DQ_26) ; also on sheet 136
M_B_DQ_27: DIMMB1.190(DQ_27) DIMMB2.190(DQ_27) ; also on sheet 136
M_B_DQ_28: DIMMB1.36(DQ_28) DIMMB2.36(DQ_28) ; also on sheet 136
M_B_DQ_29: DIMMB1.181(DQ_29) DIMMB2.181(DQ_29) ; also on sheet 136
M_B_DQ_30: DIMMB1.43(DQ_30) DIMMB2.43(DQ_30) ; also on sheet 136
M_B_DQ_31: DIMMB1.188(DQ_31) DIMMB2.188(DQ_31) ; also on sheet 136
M_B_DQ_32: DIMMB1.97(DQ_32) DIMMB2.97(DQ_32) ; also on sheet 136
M_B_DQ_33: DIMMB1.242(DQ_33) DIMMB2.242(DQ_33) ; also on sheet 136
M_B_DQ_34: DIMMB1.104(DQ_34) DIMMB2.104(DQ_34) ; also on sheet 136
M_B_DQ_35: DIMMB1.249(DQ_35) DIMMB2.249(DQ_35) ; also on sheet 136
M_B_DQ_36: DIMMB1.95(DQ_36) DIMMB2.95(DQ_36) ; also on sheet 136
M_B_DQ_37: DIMMB1.240(DQ_37) DIMMB2.240(DQ_37) ; also on sheet 136
M_B_DQ_38: DIMMB1.102(DQ_38) DIMMB2.102(DQ_38) ; also on sheet 136
M_B_DQ_39: DIMMB1.247(DQ_39) DIMMB2.247(DQ_39) ; also on sheet 136
M_B_DQ_40: DIMMB1.108(DQ_40) DIMMB2.108(DQ_40) ; also on sheet 136
M_B_DQ_41: DIMMB1.253(DQ_41) DIMMB2.253(DQ_41) ; also on sheet 136
M_B_DQ_42: DIMMB1.115(DQ_42) DIMMB2.115(DQ_42) ; also on sheet 136
M_B_DQ_43: DIMMB1.260(DQ_43) DIMMB2.260(DQ_43) ; also on sheet 136
M_B_DQ_44: DIMMB1.106(DQ_44) DIMMB2.106(DQ_44) ; also on sheet 136
M_B_DQ_45: DIMMB1.251(DQ_45) DIMMB2.251(DQ_45) ; also on sheet 136
M_B_DQ_46: DIMMB1.113(DQ_46) DIMMB2.113(DQ_46) ; also on sheet 136
M_B_DQ_47: DIMMB1.258(DQ_47) DIMMB2.258(DQ_47) ; also on sheet 136
M_B_DQ_48: DIMMB1.119(DQ_48) DIMMB2.119(DQ_48) ; also on sheet 136
M_B_DQ_49: DIMMB1.264(DQ_49) DIMMB2.264(DQ_49) ; also on sheet 136
M_B_DQ_50: DIMMB1.126(DQ_50) DIMMB2.126(DQ_50) ; also on sheet 136
M_B_DQ_51: DIMMB1.271(DQ_51) DIMMB2.271(DQ_51) ; also on sheet 136
M_B_DQ_52: DIMMB1.117(DQ_52) DIMMB2.117(DQ_52) ; also on sheet 136
M_B_DQ_53: DIMMB1.262(DQ_53) DIMMB2.262(DQ_53) ; also on sheet 136
M_B_DQ_54: DIMMB1.124(DQ_54) DIMMB2.124(DQ_54) ; also on sheet 136
M_B_DQ_55: DIMMB1.269(DQ_55) DIMMB2.269(DQ_55) ; also on sheet 136
M_B_DQ_56: DIMMB1.130(DQ_56) DIMMB2.130(DQ_56) ; also on sheet 136
M_B_DQ_57: DIMMB1.275(DQ_57) DIMMB2.275(DQ_57) ; also on sheet 136
M_B_DQ_58: DIMMB1.137(DQ_58) DIMMB2.137(DQ_58) ; also on sheet 136
M_B_DQ_59: DIMMB1.282(DQ_59) DIMMB2.282(DQ_59) ; also on sheet 136
M_B_DQ_60: DIMMB1.128(DQ_60) DIMMB2.128(DQ_60) ; also on sheet 136
M_B_DQ_61: DIMMB1.273(DQ_61) DIMMB2.273(DQ_61) ; also on sheet 136
M_B_DQ_62: DIMMB1.135(DQ_62) DIMMB2.135(DQ_62) ; also on sheet 136
M_B_DQ_63: DIMMB1.280(DQ_63) DIMMB2.280(DQ_63) ; also on sheet 136
M_B_DQS_DN_0: DIMMB1.152(DQS0_DN) DIMMB2.152(DQS0_DN) ; also on sheet 136
M_B_DQS_DN_1: DIMMB1.163(DQS1_DN) DIMMB2.163(DQS1_DN) ; also on sheet 136
M_B_DQS_DN_2: DIMMB1.174(DQS2_DN) DIMMB2.174(DQS2_DN) ; also on sheet 136
M_B_DQS_DN_3: DIMMB1.185(DQS3_DN) DIMMB2.185(DQS3_DN) ; also on sheet 136
M_B_DQS_DN_4: DIMMB1.244(DQS4_DN) DIMMB2.244(DQS4_DN) ; also on sheet 136
M_B_DQS_DN_5: DIMMB1.255(DQS5_DN) DIMMB2.255(DQS5_DN) ; also on sheet 136
M_B_DQS_DN_6: DIMMB1.266(DQS6_DN) DIMMB2.266(DQS6_DN) ; also on sheet 136
M_B_DQS_DN_7: DIMMB1.277(DQS7_DN) DIMMB2.277(DQS7_DN) ; also on sheet 136
M_B_DQS_DN_8: DIMMB1.196(DQS8_DN) DIMMB2.196(DQS8_DN) ; also on sheet 136
M_B_DQS_DN_9: DIMMB1.8(DQS9_DN) DIMMB2.8(DQS9_DN) ; also on sheet 136
M_B_DQS_DN_10: DIMMB1.19(DQS10_DN) DIMMB2.19(DQS10_DN) ; also on sheet 136
M_B_DQS_DN_11: DIMMB1.30(DQS11_DN) DIMMB2.30(DQS11_DN) ; also on sheet 136
M_B_DQS_DN_12: DIMMB1.41(DQS12_DN) DIMMB2.41(DQS12_DN) ; also on sheet 136
M_B_DQS_DN_13: DIMMB1.100(DQS13_DN) DIMMB2.100(DQS13_DN) ; also on sheet 136
M_B_DQS_DN_14: DIMMB1.111(DQS14_DN) DIMMB2.111(DQS14_DN) ; also on sheet 136
M_B_DQS_DN_15: DIMMB1.122(DQS15_DN) DIMMB2.122(DQS15_DN) ; also on sheet 136
M_B_DQS_DN_16: DIMMB1.133(DQS16_DN) DIMMB2.133(DQS16_DN) ; also on sheet 136
M_B_DQS_DN_17: DIMMB1.52(DQS17_DN) DIMMB2.52(DQS17_DN) ; also on sheet 136
M_B_DQS_DP_0: DIMMB1.153(DQS0_DP) DIMMB2.153(DQS0_DP) ; also on sheet 136
M_B_DQS_DP_1: DIMMB1.164(DQS1_DP) DIMMB2.164(DQS1_DP) ; also on sheet 136
M_B_DQS_DP_2: DIMMB1.175(DQS2_DP) DIMMB2.175(DQS2_DP) ; also on sheet 136
M_B_DQS_DP_3: DIMMB1.186(DQS3_DP) DIMMB2.186(DQS3_DP) ; also on sheet 136
M_B_DQS_DP_4: DIMMB1.245(DQS4_DP) DIMMB2.245(DQS4_DP) ; also on sheet 136
M_B_DQS_DP_5: DIMMB1.256(DQS5_DP) DIMMB2.256(DQS5_DP) ; also on sheet 136
M_B_DQS_DP_6: DIMMB1.267(DQS6_DP) DIMMB2.267(DQS6_DP) ; also on sheet 136
M_B_DQS_DP_7: DIMMB1.278(DQS7_DP) DIMMB2.278(DQS7_DP) ; also on sheet 136
M_B_DQS_DP_8: DIMMB1.197(DQS8_DP) DIMMB2.197(DQS8_DP) ; also on sheet 136
M_B_DQS_DP_9: DIMMB1.7(DQS9_DP) DIMMB2.7(DQS9_DP) ; also on sheet 136
M_B_DQS_DP_10: DIMMB1.18(DQS10_DP) DIMMB2.18(DQS10_DP) ; also on sheet 136
M_B_DQS_DP_11: DIMMB1.29(DQS11_DP) DIMMB2.29(DQS11_DP) ; also on sheet 136
M_B_DQS_DP_12: DIMMB1.40(DQS12_DP) DIMMB2.40(DQS12_DP) ; also on sheet 136
M_B_DQS_DP_13: DIMMB1.99(DQS13_DP) DIMMB2.99(DQS13_DP) ; also on sheet 136
M_B_DQS_DP_14: DIMMB1.110(DQS14_DP) DIMMB2.110(DQS14_DP) ; also on sheet 136
M_B_DQS_DP_15: DIMMB1.121(DQS15_DP) DIMMB2.121(DQS15_DP) ; also on sheet 136
M_B_DQS_DP_16: DIMMB1.132(DQS16_DP) DIMMB2.132(DQS16_DP) ; also on sheet 136
M_B_DQS_DP_17: DIMMB1.51(DQS17_DP) DIMMB2.51(DQS17_DP) ; also on sheet 136
M_B_ECC_0: DIMMB1.49(CB0) DIMMB2.49(CB0) ; also on sheet 136
M_B_ECC_1: DIMMB1.194(CB1) DIMMB2.194(CB1) ; also on sheet 136
M_B_ECC_2: DIMMB1.56(CB2) DIMMB2.56(CB2) ; also on sheet 136
M_B_ECC_3: DIMMB1.201(CB3) DIMMB2.201(CB3) ; also on sheet 136
M_B_ECC_4: DIMMB1.47(CB4) DIMMB2.47(CB4) ; also on sheet 136
M_B_ECC_5: DIMMB1.192(CB5) DIMMB2.192(CB5) ; also on sheet 136
M_B_ECC_6: DIMMB1.54(CB6) DIMMB2.54(CB6) ; also on sheet 136
M_B_ECC_7: DIMMB1.199(CB7) DIMMB2.199(CB7) ; also on sheet 136
M_B_MA_0: DIMMB1.79(A0) DIMMB2.79(A0) ; also on sheet 136
M_B_MA_1: DIMMB1.72(A1) DIMMB2.72(A1) ; also on sheet 136
M_B_MA_2: DIMMB1.216(A2) DIMMB2.216(A2) ; also on sheet 136
M_B_MA_3: DIMMB1.71(A3) DIMMB2.71(A3) ; also on sheet 136
M_B_MA_4: DIMMB1.214(A4) DIMMB2.214(A4) ; also on sheet 136
M_B_MA_5: DIMMB1.213(A5) DIMMB2.213(A5) ; also on sheet 136
M_B_MA_6: DIMMB1.69(A6) DIMMB2.69(A6) ; also on sheet 136
M_B_MA_7: DIMMB1.211(A7) DIMMB2.211(A7) ; also on sheet 136
M_B_MA_8: DIMMB1.68(A8) DIMMB2.68(A8) ; also on sheet 136
M_B_MA_9: DIMMB1.66(A9) DIMMB2.66(A9) ; also on sheet 136
M_B_MA_10: DIMMB1.225(A10) DIMMB2.225(A10) ; also on sheet 136
M_B_MA_11: DIMMB1.210(A11) DIMMB2.210(A11) ; also on sheet 136
M_B_MA_12: DIMMB1.65(A12) DIMMB2.65(A12) ; also on sheet 136
M_B_MA_13: DIMMB1.232(A13) DIMMB2.232(A13) ; also on sheet 136
M_B_MA_14: DIMMB1.228(A14/WE#) DIMMB2.228(A14/WE#) ; also on sheet 136
M_B_MA_15: DIMMB1.86(A15/CAS#) DIMMB2.86(A15/CAS#) ; also on sheet 136
M_B_MA_16: DIMMB1.82(A16/RAS#) DIMMB2.82(A16/RAS#) ; also on sheet 136
M_B_MA_17: DIMMB1.234(A17) DIMMB2.234(A17) ; also on sheet 136
M_B_ODT_0: DIMMB1.87(ODT0) ; also on sheet 136
M_B_ODT_1: DIMMB1.91(ODT1) ; also on sheet 136
M_B_ODT_2: DIMMB2.87(ODT0) ; also on sheet 136
M_B_ODT_3: DIMMB2.91(ODT1) ; also on sheet 136
M_B_PAR: DIMMB1.222(PAR) DIMMB2.222(PAR) ; also on sheet 136
NV_SAVE_CHA_DIMM1: DIMMA2.230(RFU_2) ; also on sheet 52
NV_SAVE_CHB_DIMM0: DIMMB1.230(RFU_2) ; also on sheet 52
NV_SAVE_CHB_DIMM1: DIMMB2.230(RFU_2) ; also on sheet 52
PVPP_AB: DIMMA2.139(SA0) DIMMA2.142(VPP_0) DIMMA2.143(VPP_1) DIMMA2.284(VDDSPD) DIMMA2.286(VPP_2) DIMMA2.287(VPP_3) DIMMA2.288(VPP_4) DIMMB1.142(VPP_0) DIMMB1.143(VPP_1) DIMMB1.238(SA2) DIMMB1.284(VDDSPD) DIMMB1.286(VPP_2) DIMMB1.287(VPP_3) DIMMB1.288(VPP_4) DIMMB2.139(SA0) DIMMB2.142(VPP_0) DIMMB2.143(VPP_1) DIMMB2.238(SA2) DIMMB2.284(VDDSPD) DIMMB2.286(VPP_2) DIMMB2.287(VPP_3) DIMMB2.288(VPP_4) ; also on sheet 27 98 119 160
PVTT_AB: DIMMA2.77(VTT_0) DIMMA2.221(VTT_1) DIMMB1.77(VTT_0) DIMMB1.221(VTT_1) DIMMB2.77(VTT_0) DIMMB2.221(VTT_1) ; also on sheet 29 119
SMB_DDR_AB_SCL_LVC2V5: DIMMA2.141(SCL) DIMMB1.141(SCL) DIMMB2.141(SCL) ; also on sheet 119 160
SMB_DDR_AB_SDA_LVC2V5: DIMMA2.285(SDA) DIMMB1.285(SDA) DIMMB2.285(SDA) ; also on sheet 119 160

Not connected (* = marked no-connect by the designer): DIMMA2 144(RFU_3)* 205(RFU_0)* 227(RFU_1)* NP1* NP2* NP3*; DIMMB1 144(RFU_3)* 205(RFU_0)* 227(RFU_1)* NP1* NP2* NP3*; DIMMB2 144(RFU_3)* 205(RFU_0)* 227(RFU_1)* NP1* NP2* NP3*

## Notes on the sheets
sheet 116
- DDR4 DIMM CPU0 CHB-2
- FAB1 REV021 20150424
- FAB1 REV003 20150318
- DIMMB2
- I2C Address = AA
- Chip Select Signal DIMM Mapping
- ODT Signal DIMM Mapping
- CKE Signal DIMM Mapping
- DDR4 Clock Signal DIMM Pin Mapping (UDIMM/RDIMM support)
- DIMM
- DIMM Pin
- CPU Signal
- DIMM
- DIMM Pin
- CPU Signal
- DIMM
- DIMM Pin
- CPU Signal
- DIMM
- DIMM Pin
- CPU Signal
- DIMM0
- 83
- CS_N0
- DIMM0
- 86
- ODT0
- DIMM0
- 59
- CKE0
- DIMM0
- 73
- CLK_DP0
- DIMM0
- 88
- CS_N1
- DIMM0
- 90
- ODT1
- DIMM0
- 200
- CKE1
- DIMM0
- 74
- CLK_DN0
- DIMM0
- 92
- CS_N2/C[0]
- DIMM1
- 86
- ODT2
- DIMM1
- 59
- CKE2
- DIMM0
- 215
- CLK_DP2
- DIMM0
- 234
- CS_N3/C[1]
- DIMM1
- 90
- ODT3
- DIMM1
- 200
- CKE3
- DIMM0
- 216
- CLK_DN2
- DIMM1
- 83
- CS_N4
- DIMM1
- 73
- CLK_DP1
- DIMM1
- 88
- CS_N5
- DIMM1
- 74
- CLK_DN1
- DIMM1
- 92
- CS_N6/C[3]
- DIMM1
- 215
- CLK_DP3
- DIMM1
- 234
- CS_N7/C[4]
- DIMM1
- 216
- CLK_DN3
sheet 117
- DDR4 DIMM CPU0 CHB-1
- FAB1 REV021 20150424
- FAB1 REV003 20150318
- DIMMB1
- I2C Address = A8
- Chip Select Signal DIMM Mapping
- ODT Signal DIMM Mapping
- CKE Signal DIMM Mapping
- DDR4 Clock Signal DIMM Pin Mapping (UDIMM/RDIMM support)
- DIMM
- DIMM Pin
- CPU Signal
- DIMM
- DIMM Pin
- CPU Signal
- DIMM
- DIMM Pin
- CPU Signal
- DIMM
- DIMM Pin
- CPU Signal
- DIMM0
- 83
- CS_N0
- DIMM0
- 86
- ODT0
- DIMM0
- 59
- CKE0
- DIMM0
- 73
- CLK_DP0
- DIMM0
- 88
- CS_N1
- DIMM0
- 90
- ODT1
- DIMM0
- 200
- CKE1
- DIMM0
- 74
- CLK_DN0
- DIMM0
- 92
- CS_N2/C[0]
- DIMM1
- 86
- ODT2
- DIMM1
- 59
- CKE2
- DIMM0
- 215
- CLK_DP2
- DIMM0
- 234
- CS_N3/C[1]
- DIMM1
- 90
- ODT3
- DIMM1
- 200
- CKE3
- DIMM0
- 216
- CLK_DN2
- DIMM1
- 83
- CS_N4
- DIMM1
- 73
- CLK_DP1
- DIMM1
- 88
- CS_N5
- DIMM1
- 74
- CLK_DN1
- DIMM1
- 92
- CS_N6/C[3]
- DIMM1
- 215
- CLK_DP3
- DIMM1
- 234
- CS_N7/C[4]
- DIMM1
- 216
- CLK_DN3
sheet 118
- DDR4 DIMM CPU0 CHA-2
- FAB1 REV021 20150424
- FAB1 REV003 20150318
- DIMMA2
- I2C Address = A2
- Chip Select Signal DIMM Mapping
- ODT Signal DIMM Mapping
- CKE Signal DIMM Mapping
- DDR4 Clock Signal DIMM Pin Mapping (UDIMM/RDIMM support)
- DIMM
- DIMM Pin
- CPU Signal
- DIMM
- DIMM Pin
- CPU Signal
- DIMM
- DIMM Pin
- CPU Signal
- DIMM
- DIMM Pin
- CPU Signal
- DIMM0
- 83
- CS_N0
- DIMM0
- 86
- ODT0
- DIMM0
- 59
- CKE0
- DIMM0
- 73
- CLK_DP0
- DIMM0
- 88
- CS_N1
- DIMM0
- 90
- ODT1
- DIMM0
- 200
- CKE1
- DIMM0
- 74
- CLK_DN0
- DIMM0
- 92
- CS_N2/C[0]
- DIMM1
- 86
- ODT2
- DIMM1
- 59
- CKE2
- DIMM0
- 215
- CLK_DP2
- DIMM0
- 234
- CS_N3/C[1]
- DIMM1
- 90
- ODT3
- DIMM1
- 200
- CKE3
- DIMM0
- 216
- CLK_DN2
- DIMM1
- 83
- CS_N4
- DIMM1
- 73
- CLK_DP1
- DIMM1
- 88
- CS_N5
- DIMM1
- 74
- CLK_DN1
- DIMM1
- 92
- CS_N6/C[3]
- DIMM1
- 215
- CLK_DP3
- DIMM1
- 234
- CS_N7/C[4]
- DIMM1
- 216
- CLK_DN3
